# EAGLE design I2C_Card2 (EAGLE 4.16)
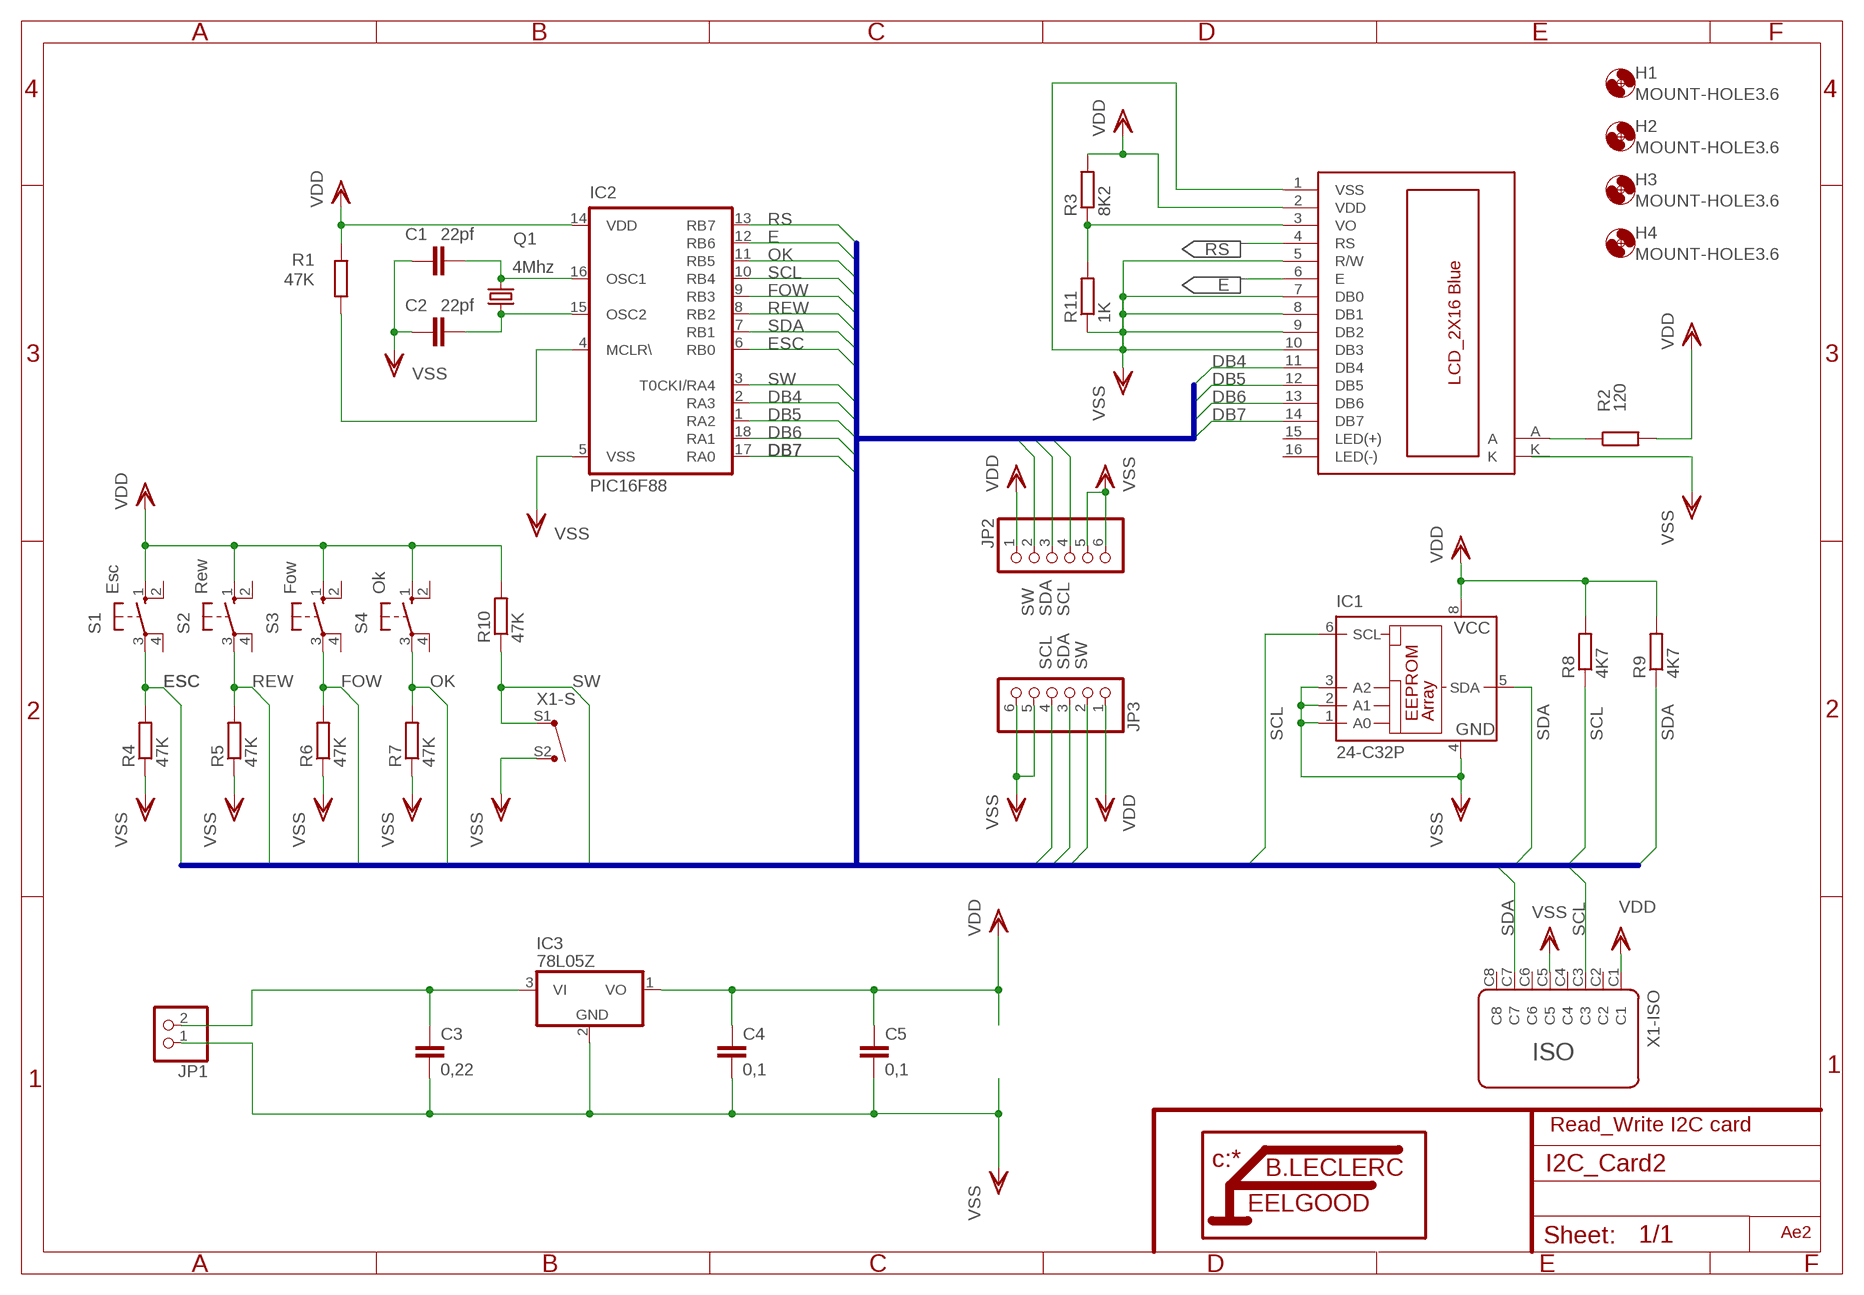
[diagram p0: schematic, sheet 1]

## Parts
C1  22pf  C-EU025-025X050  [C025-025X050]
C2  22pf  C-EU025-025X050  [C025-025X050]
C3  0,22  C-EU102-043X133  [C102-043X133]
C4  0,1  C-EU102-043X133  [C102-043X133]
C5  0,1  C-EU102-043X133  [C102-043X133]
H1  MOUNT-HOLE3.6  [3,6]
H2  MOUNT-HOLE3.6  [3,6]
H3  MOUNT-HOLE3.6  [3,6]
H4  MOUNT-HOLE3.6  [3,6]
IC1  24-C32P  [DIL8]
IC2  PIC16F88  PIC16F84AP  [DIL18]
IC3  78L05Z  [TO92]
JP1  PINHD-1X2  [1X02]
JP2  PINHD-1X6  [1X06]
JP3  PINHD-1X6  [1X06]
LCD1  LCD_2X16_DIL  [BTHQ21603V]
Q1  4Mhz  CRYTALHC49U-V  [HC49U-V]
R1  47K  R-EU_0207/10  [0207/10]
R2  120  R-EU_0207/10  [0207/10]
R3  8K2  R-EU_0207/10  [0207/10]
R4  47K  R-EU_0207/10  [0207/10]
R5  47K  R-EU_0207/10  [0207/10]
R6  47K  R-EU_0207/10  [0207/10]
R7  47K  R-EU_0207/10  [0207/10]
R8  4K7  R-EU_0207/10  [0207/10]
R9  4K7  R-EU_0207/10  [0207/10]
R10  47K  R-EU_0207/10  [0207/10]
R11  1K  R-EU_0207/10  [0207/10]
S1  Esc  10-XX  [B3F-10XX]
S2  Rew  10-XX  [B3F-10XX]
S3  Fow  10-XX  [B3F-10XX]
S4  Ok  10-XX  [B3F-10XX]
X1  C7022064  [C7022064]

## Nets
DB4: IC2.2(RA3) LCD1.11(DB4)
DB5: IC2.1(RA2) LCD1.12(DB5)
DB6: IC2.18(RA1) LCD1.13(DB6)
DB7: IC2.17(RA0) LCD1.14(DB7)
E: IC2.12(RB6) LCD1.6(E)
ESC: IC2.6(RB0) R4.2 S1.3(P)
FOW: IC2.9(RB3) R6.2 S3.3(P)
N$1: LCD1.A R2.1
N$4: C3.1 IC3.3(VI) JP1.2
N$12: IC2.4(MCLR\) R1.1
N$32: C1.2 IC2.16(OSC1) Q1.2
N$38: C2.2 IC2.15(OSC2) Q1.1
OK: IC2.11(RB5) R7.2 S4.3(P)
REW: IC2.8(RB2) R5.2 S2.3(P)
RS: IC2.13(RB7) LCD1.4(RS)
SCL: IC1.6(SCL) IC2.10(RB4) JP2.4 JP3.4 R8.1 X1.C3(-ISO:C3)
SDA: IC1.5(SDA) IC2.7(RB1) JP2.3 JP3.3 R9.1 X1.C7(-ISO:C7)
SW: IC2.3(T0CKI/RA4) JP2.2 JP3.2 R10.1 X1.S1(-S:S1)
VDD: C4.1 C5.1 IC1.8(VCC) IC2.14(VDD) IC3.1(VO) JP2.1 JP3.1 LCD1.2(VDD) R1.2 R2.2 R3.2 R8.2 R9.2 R10.2 S1.1(S) S2.1(S) S3.1(S) S4.1(S) X1.C1(-ISO:C1)
VO: LCD1.3(VO) R3.1 R11.2
VSS: C1.1 C2.1 C3.2 C4.2 C5.2 IC1.1(A0) IC1.2(A1) IC1.3(A2) IC1.4(GND) IC2.5(VSS) IC3.2(GND) JP1.1 JP2.5 JP2.6 JP3.5 JP3.6 LCD1.1(VSS) LCD1.5(R/W) LCD1.7(DB0) LCD1.8(DB1) LCD1.9(DB2) LCD1.10(DB3) R4.1 R5.1 R6.1 R7.1 R11.1 X1.C5(-ISO:C5) X1.S2(-S:S2)
Unconnected: LCD1.15(LED(+)) LCD1.16(LED(-)) LCD1.K S1.2(S1) S1.4(P1) S2.2(S1) S2.4(P1) S3.2(S1) S3.4(P1) S4.2(S1) S4.4(P1) X1.C2(-ISO:C2) X1.C4(-ISO:C4) X1.C6(-ISO:C6) X1.C8(-ISO:C8) X1.C_1(-AFNOR:C1) X1.C_2(-AFNOR:C2) X1.C_3(-AFNOR:C3) X1.C_4(-AFNOR:C4) X1.C_5(-AFNOR:C5) X1.C_6(-AFNOR:C6) X1.C_7(-AFNOR:C7) X1.C_8(-AFNOR:C8)

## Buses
B$1

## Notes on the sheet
- Read_Write I2C card
- Ae2

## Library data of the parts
C1-C5 = rcl:C-EU: CAPACITOR, European symbol
H1-H4 = holes:MOUNT-HOLE: MOUNTING HOLE with drill center marker
IC1 = microchip:24-*: Serial EEPROM 32 K/64 K, 1.8 V, I2C
IC2 = microchip:PIC16F8*: MICROCONTROLLER 8-Bit PIC16F8X Family - CMOS Flash/EEPROM Pin Compatible : PIC16F83, PIC16CR83, PIC16F84A, PIC16CR84 see also PIC16C*
IC3 = linear:78*: Positive VOLTAGE REGULATOR Source: http://cache.national.com/ds/LM/LM78L05.pdf http://www.fairchildsemi.com/ds/LM/LM7805.pdf
JP1 = pinhead:PINHD-1X2: PIN HEADER
JP2 JP3 = pinhead:PINHD-1X6: PIN HEADER
LCD1 = lcd_2x16_led_backlight:LCD_2X16_DIL
Q1 = crystal:CRYTAL: CRYSTAL
R1-R11 = rcl:R-EU_: RESISTOR, European symbol
S1-S4 = switch-omron:10-XX: OMRON SWITCH
X1 = con-amphenol:C7022064: AMPHENOL CONNECTOR

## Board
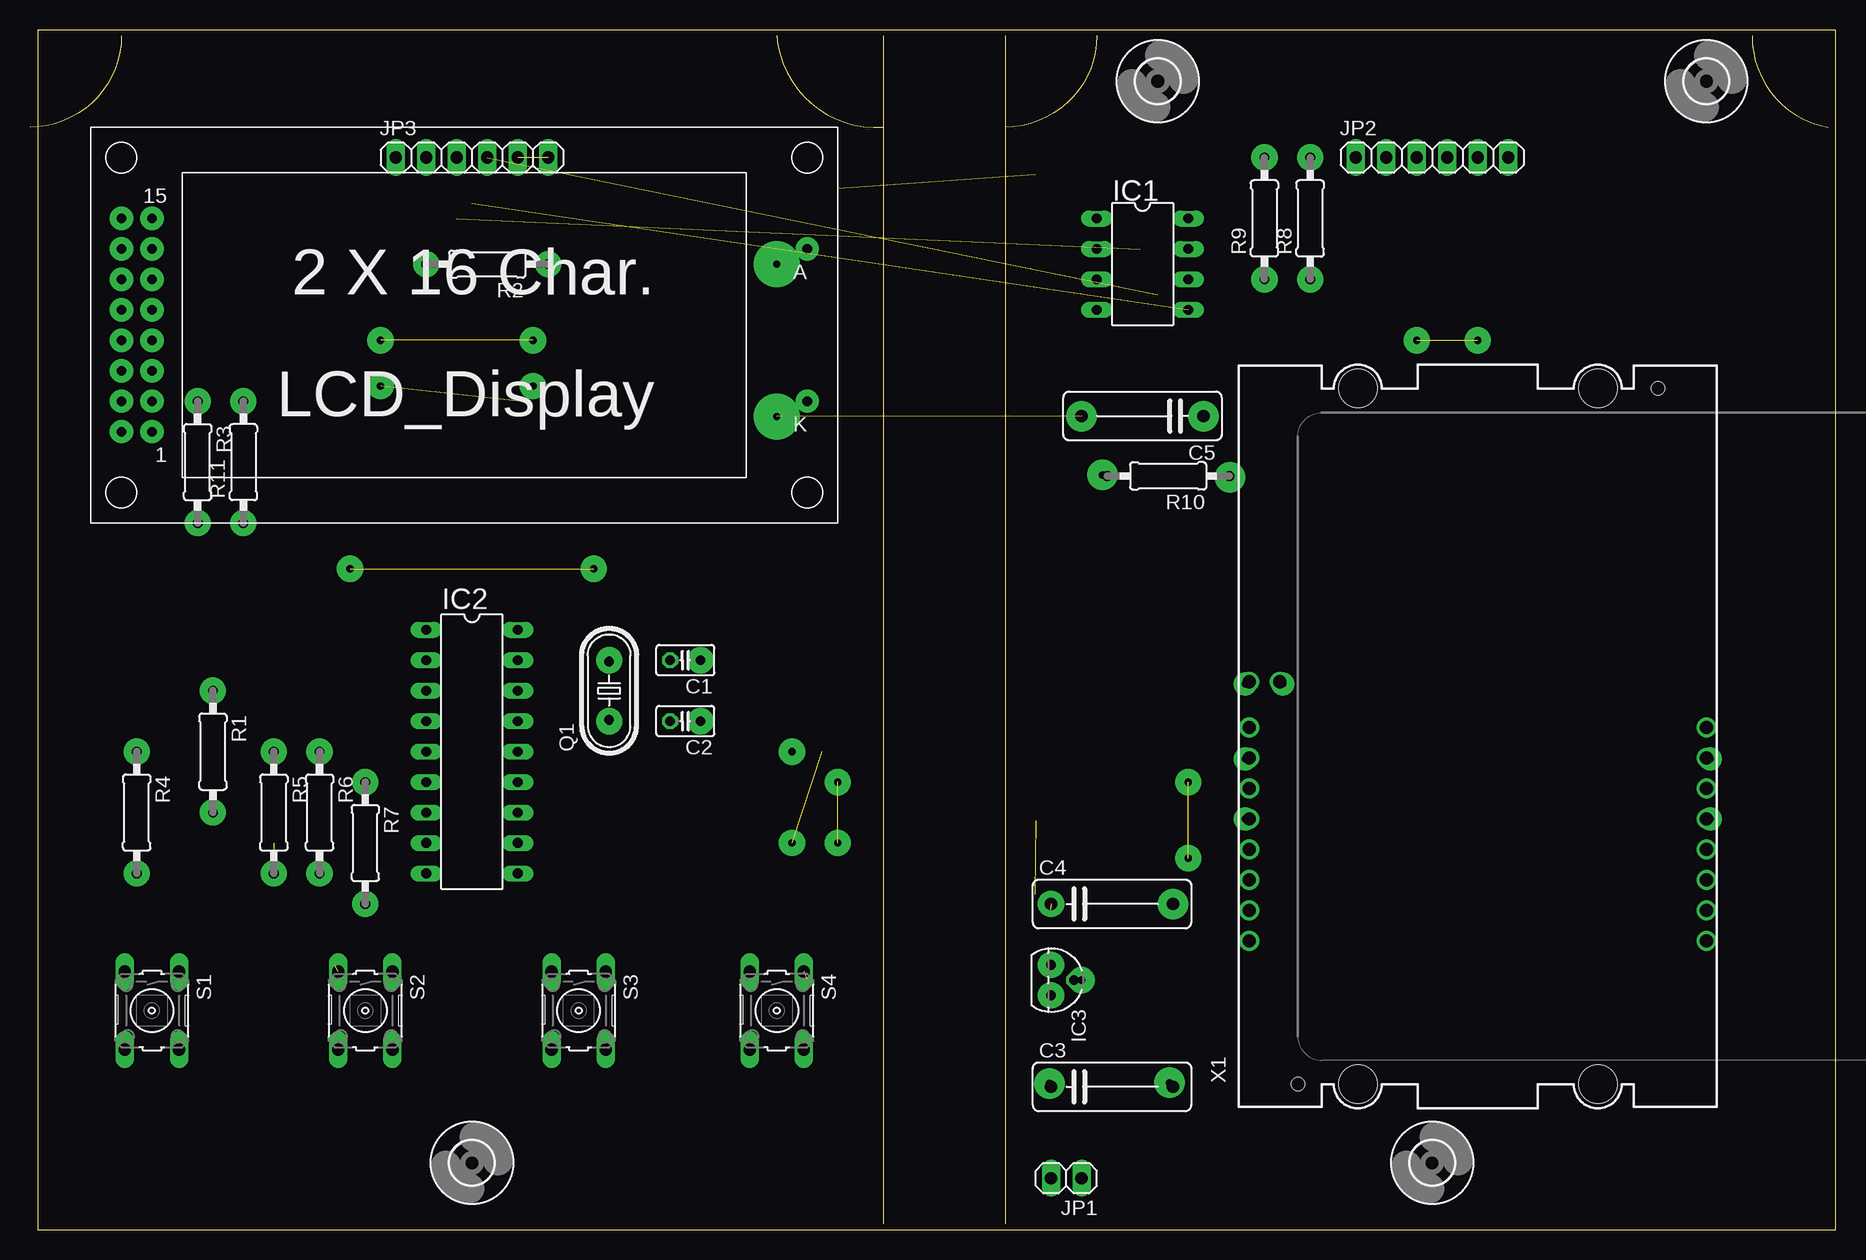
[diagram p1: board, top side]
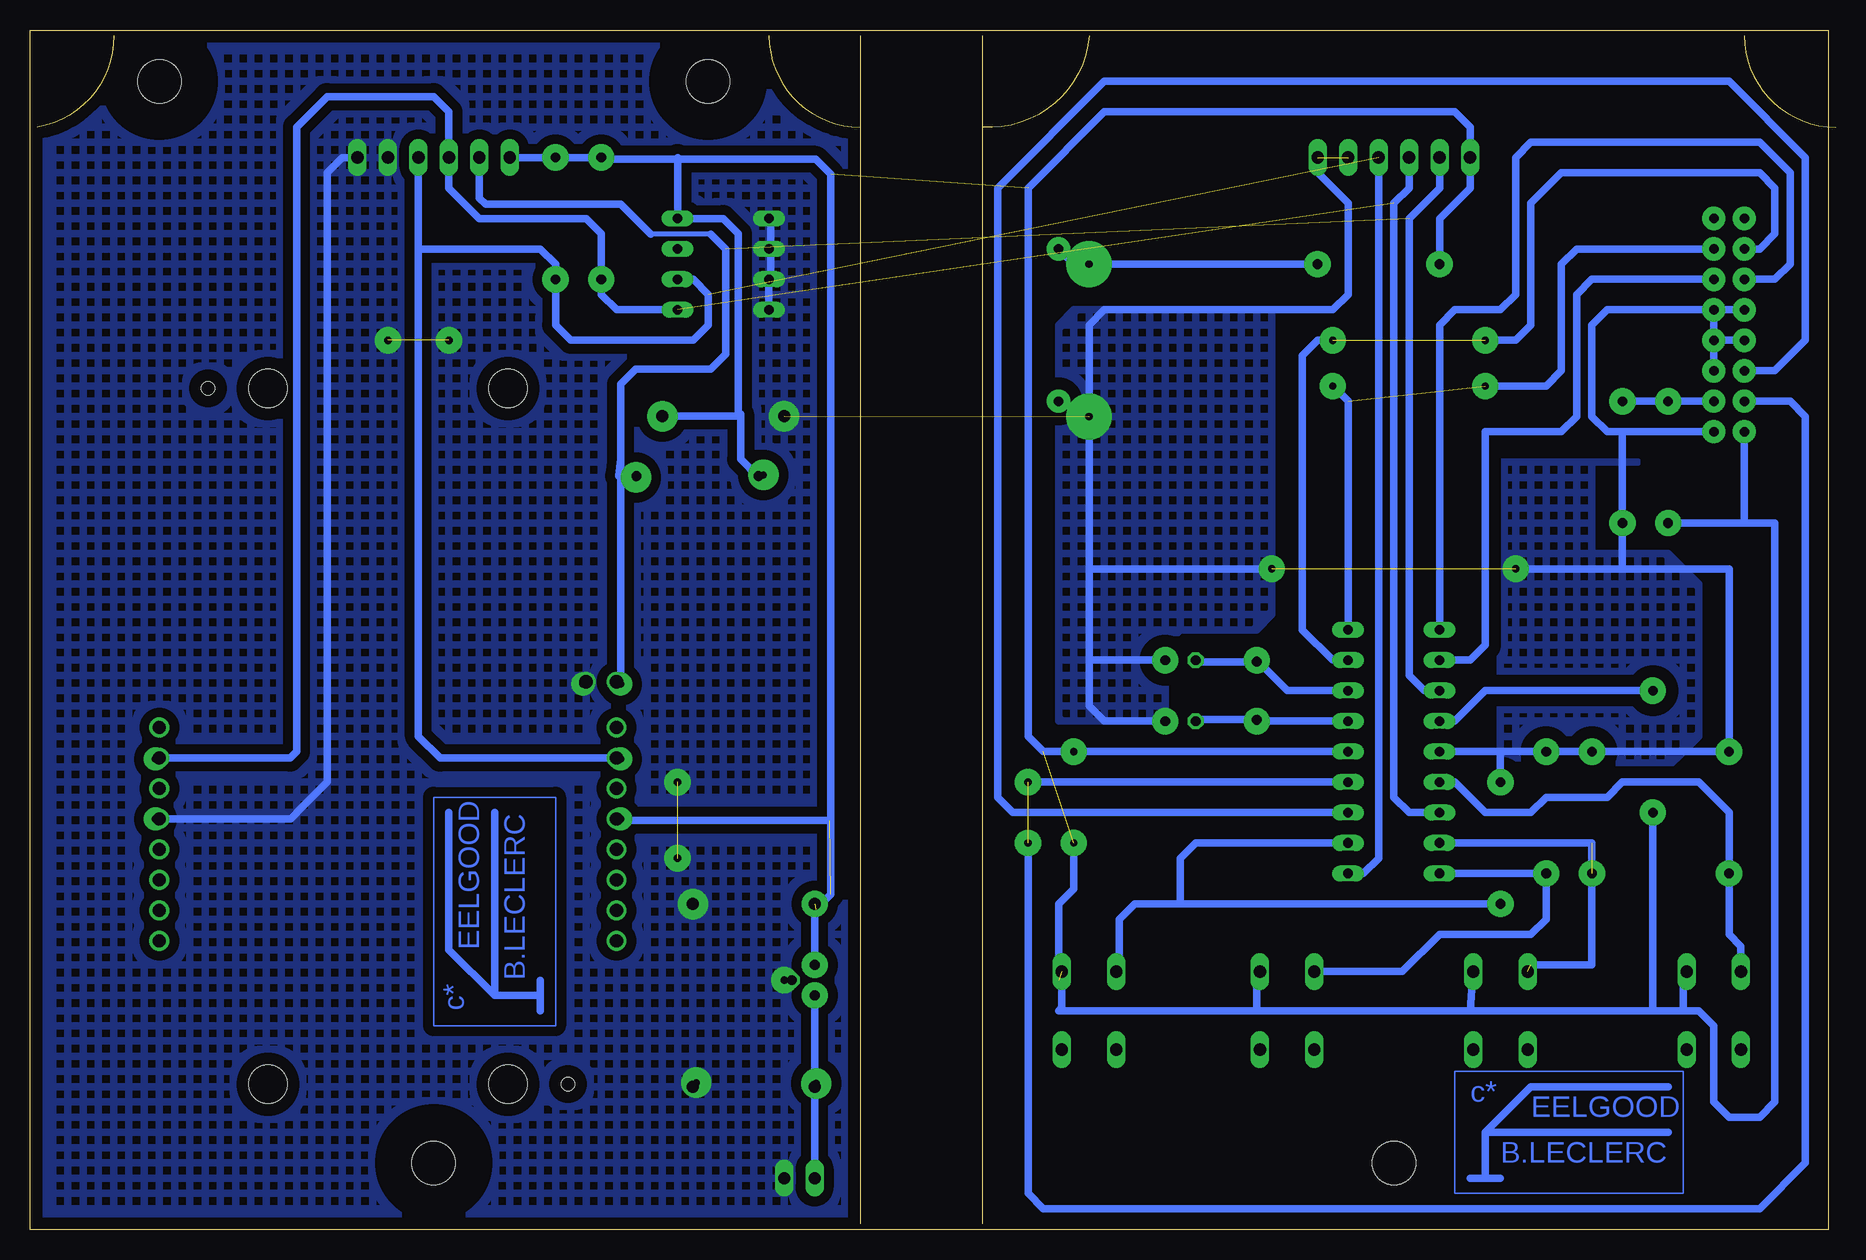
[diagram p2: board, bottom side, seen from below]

Size 150.48 x 100 mm. Coordinates in mm from the lower left corner, seen from the top.
Outline: 71.12,99.53 71.12,91.91
Outline: 71.12,91.91 71.12,0.47
Outline: 81.28,99.53 81.28,91.91
Outline: 81.28,91.91 81.28,0.47
Outline: 88.9,99.53 arc-90 81.28,91.91
Outline: 7.62,99.53 arc-90 0,91.91
Outline: 62.23,99.53 arc90 71.12,91.91
Outline: 143.51,99.53 arc81 149.86,91.91
Outline: 0.64,0 150.48,0 150.48,100 0.64,100 0.64,0
Copper layers (1*16): Top 0.035mm / dielectric 1.5mm / Bottom 0.035mm
Design rules "default": minimum track width 10mil, minimum drill 24mil, track to track 8mil, track to pad 8mil, pad to pad 8mil, via to via 8mil, smd to smd 8mil, copper to edge 40mil, drill to drill 8mil, minimum pad ring 10mil, minimum via ring 8mil, stop-mask expansion 4mil, vias tented up to drill 0mil, thermal gap 10mil

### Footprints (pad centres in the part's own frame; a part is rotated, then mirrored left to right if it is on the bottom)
C025-025X050 = drill 0.813 octagon: 1 -1.27,0; 2 1.27,0
C102-043X133 = drill 1.016 octagon: 1 -5.08,0; 2 5.08,0
3,6 = hole 3.6: 0,0
DIL8 = drill 0.813 long: 1 -3.81,-3.81; 2 -1.27,-3.81; 3 1.27,-3.81; 4 3.81,-3.81; 5 3.81,3.81; 6 1.27,3.81; 7 -1.27,3.81; 8 -3.81,3.81
DIL18 = drill 0.813 long: 1 -10.16,-3.81; 2 -7.62,-3.81; 3 -5.08,-3.81; 4 -2.54,-3.81; 5 0,-3.81; 6 2.54,-3.81; 7 5.08,-3.81; 8 7.62,-3.81; 9 10.16,-3.81; 10 10.16,3.81; 11 7.62,3.81; 12 5.08,3.81; 13 2.54,3.81; 14 0,3.81; 15 -2.54,3.81; 16 -5.08,3.81; 17 -7.62,3.81; 18 -10.16,3.81
TO92 = drill 0.813 octagon: 1 -1.27,0; 2 0,1.905; 3 1.27,0
1X02 = drill 1.016 long: 1 -1.27,0; 2 1.27,0
1X06 = drill 1.016 long: 1 -6.35,0; 2 -3.81,0; 3 -1.27,0; 4 1.27,0; 5 3.81,0; 6 6.35,0
BTHQ21603V = drill 0.8 pad 1.93 round: 1 0,8.89; 2 2.54,8.89; 3 0,6.35; 4 2.54,6.35; 5 0,3.81; 6 2.54,3.81; 7 0,1.27; 8 2.54,1.27; 9 0,-1.27; 10 2.54,-1.27; 11 0,-3.81; 12 2.54,-3.81; 13 0,-6.35; 14 2.54,-6.35; 15 0,-8.89; 16 2.54,-8.89; A -54.61,-6.35; K -54.61,6.35
HC49U-V = drill 0.813 round: 1 -2.413,0; 2 2.413,0
0207/10 = drill 0.813 octagon: 1 -5.08,0; 2 5.08,0
B3F-10XX = drill 1.016 long: 1 -3.251,2.261; 2 3.251,2.261; 3 -3.251,-2.261; 4 3.251,-2.261
C7022064 = drill 1.1 round: C1 -19.05,-6.88; C2 -19.05,-4.34; C3 -19.05,-1.8; C4 -19.05,0.74; C5 19.05,-6.88; C6 19.05,-4.34; C7 19.05,-1.8; C8 19.05,0.74; C_1 19.05,-9.42; C_2 19.05,-11.96; C_3 19.05,-14.5; C_4 19.05,-17.04; C_5 -19.05,-9.42; C_6 -19.05,-11.96; C_7 -19.05,-14.5; C_8 -19.05,-17.04; S1 -19.05,4.55; S2 -16.51,4.55 | hole 3.2: -10,-29; 10,-29; 10,29; -10,29 | hole 1.1: -15,-29; 15,29

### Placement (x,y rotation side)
C1  54.61,47.46 180 top
C2  54.61,42.38 180 top
C3  90.17,11.9 0 top
C4  90.17,27.14 0 top
C5  92.71,67.82 180 top
H1  36.83,5.55 0 top
H2  116.84,5.55 0 top
H3  93.98,95.72 0 top
H4  139.7,95.72 0 top
IC1  92.71,80.48 270 top
IC2  36.83,39.84 270 top
IC3  85.09,20.79 270 top
JP1  86.36,4.28 180 top
JP2  116.84,89.37 0 top
JP3  36.83,89.37 0 top
LCD1  10.16,75.4 180 top
Q1  48.26,44.92 90 top
R1  15.24,39.84 270 top
R2  38.1,80.48 180 top
R3  13.97,63.97 270 top
R4  8.89,34.76 270 top
R5  20.32,34.76 270 top
R6  24.13,34.76 270 top
R7  27.94,32.22 270 top
R8  106.68,84.29 90 top
R9  102.87,84.29 90 top
R10  94.85,62.82 180 top
R11  17.78,63.97 90 top
S1  10.16,18.25 270 top
S2  27.94,18.25 270 top
S3  45.72,18.25 270 top
S4  62.23,18.25 270 top
U$2  [LITTFEEL]  104.14,19.52 90 bottom
U$3  [LITTFEEL]  29.21,0.47 0 bottom
X1  120.65,41.11 0 top

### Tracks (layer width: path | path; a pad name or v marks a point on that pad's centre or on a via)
DB4
  Bottom 0.61: LCD1.11 20.32,79.21 21.59,77.94 21.59,67.78 22.86,66.51 29.21,66.51 29.21,48.73 30.48,47.46 IC2.2
DB5
  Bottom 0.61: LCD1.12 5.08,79.21 3.81,80.48 3.81,88.1 6.35,90.64 25.4,90.64 26.67,89.37 26.67,77.94 27.94,76.67 31.75,76.67 33.02,75.4 IC2.1
DB6  (1 unrouted)
  Bottom 0.61: IC2.18 40.64,69.05 41.91,70.32 | LCD1.13 21.59,81.75 22.86,80.48 22.86,71.59 24.13,70.32 29.21,70.32
DB7  (1 unrouted)
  Bottom 0.61: LCD1.14 6.35,81.75 5.08,83.02 5.08,86.83 6.35,88.1 22.86,88.1 25.4,85.56 25.4,75.4 26.67,74.13 29.21,74.13 | IC2.17 41.91,47.46 44.45,50 44.45,72.86 43.18,74.13 41.91,74.13
E
  Bottom 0.61: LCD1.6 5.08,71.59 2.54,74.13 2.54,89.37 8.89,95.72 60.96,95.72 69.85,86.83 69.85,36.03 68.58,34.76 IC2.12
ESC
  Bottom 0.61: S1.3 7.9,23.61 8.89,24.6 R4.2 8.89,34.76 11.43,37.3 17.78,37.3 19.05,36.03 24.13,36.03 25.4,34.76 29.21,34.76 31.75,37.3 IC2.6
FOW
  Bottom 0.61: IC2.9 R6.2 24.13,25.87 25.4,24.6 33.02,24.6 36.12,21.5 S3.3
N$1
  Bottom 0.61: LCD1.A 63.5,80.48 R2.1
N$2  (via drill 0.6 pad 2.54)
  other vias: 100,62.7
N$3  (via drill 0.6 pad 2.18)
  other vias: 41.91,74.13
N$4
  Bottom 0.61: JP1.2 C3.1 IC3.3
N$5  (via drill 0.6 pad 2.54)
  other vias: 97.79,67.78
N$6  (via drill 0.6 pad 2.18)
  other vias: 33.02,80.48
N$7  (via drill 0.6 pad 3.81)
  other vias: 62.23,80.48
N$8  (via drill 0.6 pad 2.18)
  other vias: 43.18,80.48
N$9  (via drill 0.6 pad 2.18)
  other vias: 29.21,74.13
N$10  (via drill 0.6 pad 2.18)
  other vias: 41.91,70.32
N$11  (via drill 0.6 pad 2.54)
  other vias: 89.38,62.91
N$12
  Bottom 0.61: R1.1 29.21,44.92 31.75,42.38 IC2.4
N$13  (via drill 0.6 pad 2.18)
  other vias: 29.21,70.32
N$14  (via drill 0.6 pad 2.54)
  other vias: 84.96,12.18
N$15  (via drill 0.6 pad 2.18)
  other vias: 63.5,39.84
N$16  (via drill 0.6 pad 1.93)
  other vias: 101.27,39.22
N$17  (via drill 0.6 pad 1.93)
  other vias: 101.27,34.22
N$18  (via drill 0.6 pad 1.93)
  other vias: 140.02,39.22
N$19  (via drill 0.6 pad 1.93)
  other vias: 140.02,34.22
N$20  (via drill 0.6 pad 2.18)
  other vias: 85.09,27.14
N$21  (via drill 0.6 pad 2.18)
  other vias: 55.88,47.46
N$22  (via drill 0.6 pad 2.18)
  other vias: 102.87,79.21
N$23  (via drill 0.6 pad 2.18)
  other vias: 102.87,89.37
N$24  (via drill 0.6 pad 2.18)
  other vias: 106.68,79.21
N$25  (via drill 0.6 pad 2.18)
  other vias: 106.68,89.37
N$26  (via drill 0.6 pad 2.18)
  other vias: 85.09,22.06
N$27  (via drill 0.6 pad 2.18)
  other vias: 85.09,19.52
N$29  (via drill 0.6 pad 2.18)
  other vias: 13.97,69.05
N$30  (via drill 0.6 pad 2.18)
  other vias: 17.78,69.05
N$31  (via drill 0.6 pad 2.18)
  other vias: 13.97,58.89
N$32
  Bottom 0.61: IC2.16 45.72,44.92 48.26,47.46 Q1.2 53.21,47.33 C1.2
N$33  (via drill 0.6 pad 2.18)
  other vias: 48.26,47.46
N$34  (via drill 0.6 pad 2.18)
  other vias: 27.94,37.3
N$35  (via drill 0.6 pad 2.18)
  other vias: 27.94,27.14
N$36  (via drill 0.6 pad 2.18)
  other vias: 20.32,29.68
N$37  (via drill 0.6 pad 2.18)
  other vias: 15.24,34.76
N$38
  Bottom 0.61: IC2.15 48.26,42.38 Q1.1 53.21,42.51 C2.2
N$39  (via drill 0.6 pad 2.18)
  other vias: 15.24,44.92
N$40  (via drill 0.6 pad 2.18)
  other vias: 8.89,39.84
N$41  (via drill 0.6 pad 2.18)
  other vias: 8.89,29.68
N$42  (via drill 0.6 pad 2.18)
  other vias: 20.32,39.84
N$43  (via drill 0.6 pad 2.18)
  other vias: 24.13,39.84
N$44  (via drill 0.6 pad 2.18)
  other vias: 24.13,29.68
N$45  (via drill 0.6 pad 2.18)
  other vias: 48.26,42.38
N$46  (via drill 0.6 pad 2.18)
  other vias: 17.78,58.89
OK
  Bottom 0.61: IC2.11 53.34,32.22 54.61,30.95 54.61,27.14 | S4.3 59.97,21.78 59.69,22.06 59.69,25.87 58.42,27.14 54.61,27.14 | R7.2 54.61,27.14
REW  (2 unrouted)
  Bottom 0.61: IC2.8 20.32,32.22 20.32,22.06 25.4,22.06
RS  (via drill 0.6 pad 2.18)  (1 unrouted)
  Bottom 0.61: LCD1.4 3.81,69.05 2.54,67.78 2.54,5.55 6.35,1.74 66.04,1.74 67.31,3.01 v67.31,32.22 | IC2.13 v67.31,37.3
SCL  (1 unrouted)
  Bottom 0.61: 118.11,81.75 JP2.4 | 118.11,81.75 107.95,81.75 106.68,80.48 R8.1 106.68,75.4 105.41,74.13 95.23,74.13 93.96,75.4 93.96,77.94 95.23,79.21 IC1.6 | X1.C3 116.31,39.31 118.11,41.11 118.11,81.75 | JP3.4 38.1,30.95 39.37,29.68 IC2.10
SDA  (1 unrouted)
  Bottom 0.61: IC1.5 101.6,76.67 102.87,77.94 R9.1 102.87,83.02 104.14,84.29 113.03,84.29 115.57,86.83 JP2.3 115.57,93.18 116.84,94.45 125.73,94.45 128.27,91.91 128.27,39.84 128.8,39.31 X1.C7 | JP3.3 35.56,86.83 36.83,85.56 36.83,36.03 35.56,34.76 IC2.7
SW  (via drill 0.6 pad 1.93)  (1 unrouted)
  Bottom 0.406: 93.77,82.97 98.77,82.97
  Bottom 0.61: R10.1 101.42,62.82 101.27,64.22 | X1.S1 101.46,45.66 v101.27,45.47 101.27,64.22 | JP2.2 113.03,85.98 112.52,85.47 101.27,85.47 98.77,82.97 | 101.27,64.22 101.27,70.47 100.02,71.72 93.77,71.72 92.52,72.97 92.52,81.72 93.77,82.97 | JP3.2 33.02,86.83 35.56,84.29 35.56,46.19 34.29,44.92 IC2.3
VDD  (via drill 0.6 pad 2.18)  (5 unrouted)
  Bottom 0.61: JP2.1 R8.2 R9.2 102.67,89.37 102.52,89.22 96.52,89.22 | 91.44,67.97 91.44,83.02 92.71,84.29 IC1.8 96.52,89.22 | 91.44,67.97 91.44,67.82 C5.1 | IC3.1 C4.1 | 83.84,34.12 85.72,34.12 101.6,34.12 X1.C1 | R10.2 89.87,62.82 91.27,64.22 91.27,67.97 91.44,67.97 | 96.52,89.22 85.02,89.22 83.77,87.97 83.77,27.95 85.02,26.7 | 96.52,89.22 96.52,89.37 | S1.1 12.42,22.06 12.7,22.06 12.7,18.25 | S2.1 30.2,21.78 30.48,18.25 | 12.7,18.25 15.24,18.25 | 15.24,18.25 30.48,18.25 | S4.1 64.49,18.53 64.77,18.25 48.26,18.25 | 30.48,18.25 48.26,18.25 | S3.1 47.98,21.07 48.26,20.79 48.26,18.25 | IC2.14 59.69,39.84 66.04,39.84 67.31,41.11 67.31,86.83 60.96,93.18 31.75,93.18 30.48,91.91 JP3.1 30.48,86.83 33.02,84.29 R2.2 | v63.5,32.22 63.5,28.41 64.77,27.14 64.77,20.79 | 15.24,18.25 R1.2 | 7.62,58.89 LCD1.2 | 7.62,58.89 R3.2 | 7.62,58.89 5.08,58.89 5.08,10.63 6.35,9.36 8.89,9.36 10.16,10.63 10.16,16.98 11.43,18.25 12.7,18.25
VO
  Bottom 0.61: LCD1.3 R3.1 R11.2
VSS  (via drill 0.6 pad 1.93, 0.6 pad 2.18, 0.6 pad 2.54, 0.6 pad 3.81)  (5 unrouted)
  Bottom 0.406: C4.2 95.25,28.2 95.02,27.97
  Bottom 0.61: IC1.1 88.84,84.29 88.77,84.22 88.77,81.72 | 88.77,81.72 88.8,81.75 IC1.2 | 88.77,81.72 88.77,79.34 IC1.3 IC1.4 | JP2.6 124.46,89.37 125.73,88.1 125.73,37.3 128.27,34.76 128.27,34.72 128.77,34.22 139.4,34.22 139.41,34.23 X1.C5 | LCD1.9 LCD1.10 | LCD1.7 LCD1.8 | LCD1.9 LCD1.7 | LCD1.7 LCD1.5 | 17.78,66.51 LCD1.1 | 17.78,66.51 19.05,66.51 20.32,67.78 20.32,75.4 19.05,76.67 LCD1.9 | JP3.6 43.18,88.1 40.64,85.56 40.64,77.94 41.91,76.67 60.96,76.67 62.23,75.4 v62.23,67.78 62.23,55.08 | 17.78,66.51 R11.1 17.78,55.08 | 27.94,39.84 R6.1 R5.1 R4.1 8.89,55.08 17.78,55.08 | 27.94,39.84 IC2.5 | 27.94,39.84 R7.1 | 62.23,47.46 62.23,43.65 60.96,42.38 C2.1 | 62.23,47.46 62.23,55.08 | 17.78,55.08 v26.67,55.08 | 62.23,55.08 v46.99,55.08 | 62.23,47.46 C1.1
  other vias: 94.96,12.24 87.63,20.79 95.25,27.14 104.39,45.47 87.63,67.78 115.57,74.13 120.65,74.13 96.52,37.3 96.52,30.95 55.88,42.38
  pour Bottom (isolate 0.813, no thermals, hatched): 82.55,99.53 149.86,99.53 149.86,0.47 81.28,0.47 81.28,99.53
  pour Bottom (isolate 1.016, no thermals, hatched): 16.51,63.97 27.94,63.97 27.94,38.57 29.21,37.3 15.24,37.3 11.43,41.11 11.43,53.81 13.97,56.35 20.32,56.35 20.32,63.97
  pour Bottom (isolate 1.016, no thermals, hatched): 45.72,76.67 63.5,76.67 64.77,75.4 64.77,42.38 57.15,42.38 55.88,42.38 55.88,47.46 55.88,48.73 54.61,50 48.26,50 46.99,51.27 46.99,76.67 48.26,76.67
